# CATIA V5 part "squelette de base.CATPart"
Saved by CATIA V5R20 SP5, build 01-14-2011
Part number: squelette de base
Bounding box of the stored display mesh (mm): x 0 to 10834.35, y 0 to 0, z 0 to 12365.631
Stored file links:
  M:\EU_thinkMotion\IAO_2010\iao\IAO_MMS_Groupe1\Problemes\gduval\Gduval\train d'aterrissage squelette + piece kinematic\squelette de base.CATPart
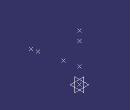
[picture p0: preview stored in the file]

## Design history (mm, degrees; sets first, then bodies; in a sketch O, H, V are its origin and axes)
Body1 (main body)
  Point1: (0, 0, 0)
  Point2: type OnPlane, Support zx-plane, H 0, V 3519.877, Direction (-1, 0, 0)
  Point3: type OnPlane, Support zx-plane, H 0, V 8460.769, Direction (-1, 0, 0)
  Point4: type OnPlane, Support zx-plane, H 0, V 10472.604, Direction (-1, 0, 0)
  Point5: type OnPlane, Support zx-plane, H -10834.35, V 12365.631, Direction (-1, 0, 0)
  Point6: type OnPlane, Support zx-plane, H -3562.187, V 6428.24, Direction (-1, 0, 0)
  Point7: type OnPlane, Support zx-plane, H -9261.784, V 11081.702, Direction (-1, 0, 0)
  Plane1: type Offset, RefPlane zx-plane, Offset 0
